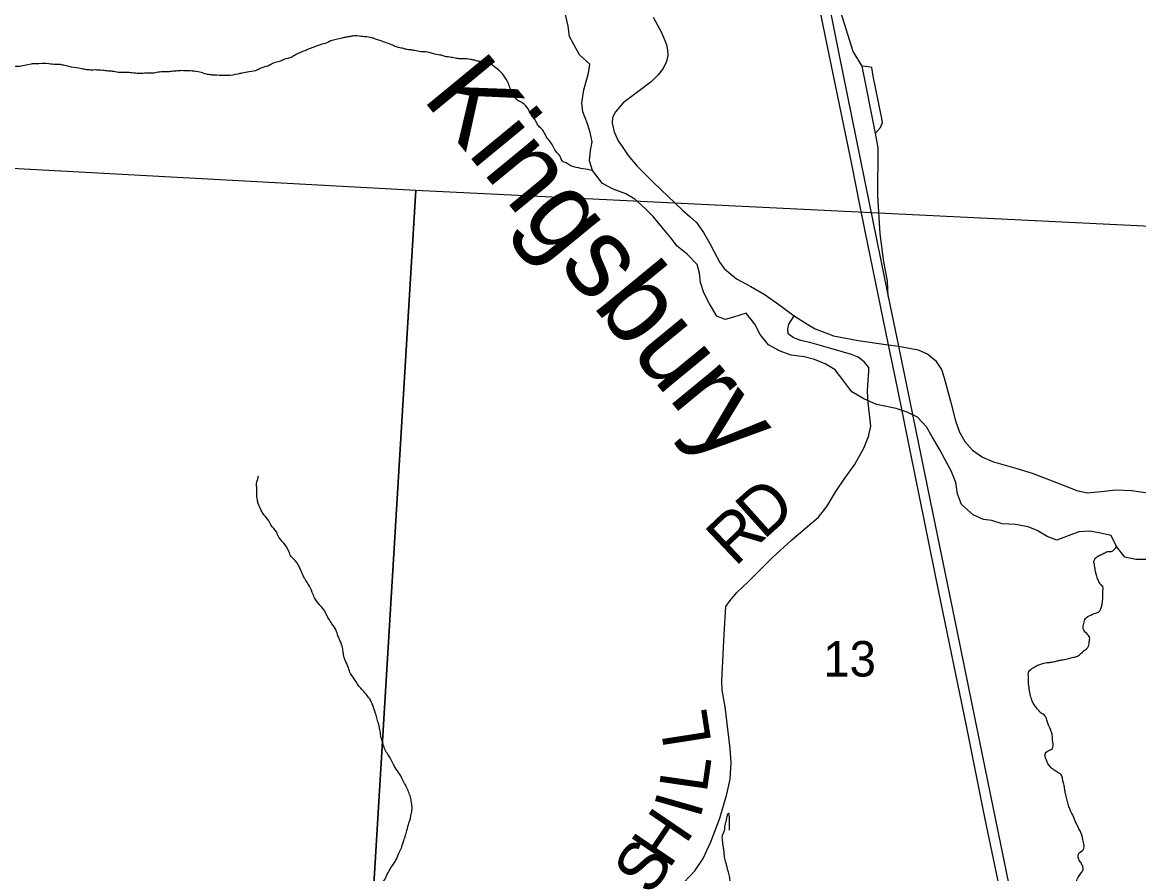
# Model space of a CAD drawing. Extents: x -20.2 to 34, y 0 to 22.
# Drawn here: x 4.435 to 5.753, y 19.304 to 20.309 of the extents above; entities that cross this region are included whole.
import ezdxf

# ---------------------------------------------------------------- set-up
doc = ezdxf.new("R2010")
doc.units = 0
for name, color, linetype in [('GM_X_County_Road', 7, 'Continuous'), ('GM_X_Interchange_Ramps', 7, 'Continuous'), ('GM_X_Minor_River', 7, 'Continuous'), ('GM_X_Minor_River_Text', 7, 'Continuous'), ('GM_X_Section', 7, 'Continuous'), ('GM_X_Section_Text', 7, 'Continuous'), ('GM_X_Township_Road', 7, 'Continuous'), ('GM_X_Township_Road_Text', 7, 'Continuous'), ('GM_X_US_Route', 7, 'Continuous')]:
    doc.layers.add(name, color=color, linetype=linetype)

msp = doc.modelspace()

# ---------------------------------------------------------------- linework, layer by layer
at = {"layer": 'GM_X_County_Road'}
for points in [[(5.1796, 20.3146), (5.1893, 20.2966), (5.1953, 20.2825), (5.1964, 20.2756), (5.1969, 20.2695), (5.1954, 20.2626), (5.1914, 20.2542), (5.1857, 20.2467), (5.1771, 20.2385), (5.1442, 20.2135), (5.135, 20.2031), (5.1315, 20.1964), (5.1313, 20.1896), (5.1338, 20.1793), (5.1383, 20.1688), (5.1429, 20.1623), (5.1502, 20.1516), (5.1607, 20.1388), (5.18, 20.1195), (5.2142, 20.0871), (5.2233, 20.0792), (5.2308, 20.0724), (5.2392, 20.0605), (5.2467, 20.0478), (5.2515, 20.0377), (5.2583, 20.0252), (5.2635, 20.0182), (5.269, 20.0134), (5.2779, 20.0061), (5.2948, 19.9968), (5.3118, 19.987), (5.3215, 19.9803)], [(5.3215, 19.9803), (5.3264, 19.977), (5.346, 19.9624), (5.3624, 19.9521), (5.371, 19.9471), (5.3925, 19.9389), (5.4216, 19.9333), (5.4571, 19.9282), (5.4692, 19.9264), (5.4925, 19.9223), (5.5038, 19.9171), (5.5131, 19.9096), (5.52, 19.8992), (5.5232, 19.889), (5.5307, 19.8616), (5.5365, 19.8384), (5.5411, 19.8249), (5.5475, 19.8142), (5.5567, 19.8038), (5.5686, 19.7954), (5.5813, 19.7899), (5.6033, 19.7839)], [(5.6033, 19.7839), (5.609, 19.7824), (5.6272, 19.7766), (5.6579, 19.765), (5.6799, 19.7561), (5.692, 19.7535), (5.7085, 19.7549), (5.7258, 19.7569), (5.7443, 19.7561), (5.7692, 19.7529), (5.8276, 19.7468), (5.8444, 19.7422), (5.8961, 19.7358), (5.9368, 19.7289), (5.9539, 19.7269), (5.9724, 19.7277), (6.0057, 19.7309)]]:
    msp.add_lwpolyline(points, dxfattribs=at)
at = {"layer": 'GM_X_Interchange_Ramps'}
for points in [[(5.4572, 19.9851), (5.4563, 20.0035), (5.4519, 20.0259), (5.4477, 20.0591), (5.4449, 20.1039), (5.4452, 20.1606), (5.4421, 20.1778), (5.4262, 20.2571), (5.4159, 20.2744), (5.4034, 20.3131), (5.3917, 20.3488), (5.3772, 20.3971), (5.3736, 20.413), (5.3672, 20.4403), (5.3555, 20.4861)], [(5.4421, 20.1778), (5.448, 20.1847), (5.4505, 20.1903), (5.4493, 20.1973), (5.4393, 20.2452), (5.4379, 20.2552), (5.4335, 20.2563), (5.4262, 20.2571)]]:
    msp.add_lwpolyline(points, dxfattribs=at)
at = {"layer": 'GM_X_Minor_River'}
for points in [[(5.7204, 19.703), (5.7079, 19.706), (5.6951, 19.7082), (5.6823, 19.7073), (5.6694, 19.7027), (5.6563, 19.6977), (5.6449, 19.7018), (5.6328, 19.7089), (5.6222, 19.7134), (5.6074, 19.7163), (5.5916, 19.7169), (5.5795, 19.721), (5.5696, 19.7221), (5.5575, 19.7277), (5.5438, 19.7397), (5.5389, 19.7522), (5.5369, 19.7658), (5.5315, 19.7794), (5.5243, 19.7923), (5.5178, 19.8051), (5.509, 19.8194), (5.5025, 19.8315), (5.4915, 19.8428), (5.4794, 19.8488), (5.4665, 19.8529), (5.4533, 19.8558), (5.4434, 19.8577), (5.4283, 19.8644), (5.4143, 19.8726), (5.4048, 19.8851), (5.3945, 19.8986), (5.3827, 19.9058), (5.3702, 19.911), (5.3578, 19.9139), (5.3426, 19.9161), (5.3294, 19.9206), (5.3157, 19.928), (5.3059, 19.9405), (5.2997, 19.9526), (5.2895, 19.9654), (5.2744, 19.9607), (5.2646, 19.958), (5.2547, 19.9621), (5.2463, 19.9765), (5.2395, 19.9893), (5.2356, 20.0018), (5.2344, 20.0127), (5.2317, 20.023), (5.2196, 20.035), (5.2078, 20.0444), (5.2006, 20.0542), (5.1907, 20.0663), (5.1796, 20.0794), (5.1701, 20.0889), (5.158, 20.1001), (5.1474, 20.1061), (5.1326, 20.1117), (5.1197, 20.1184), (5.1079, 20.1339), (5.1045, 20.1452), (5.1055, 20.1574), (5.1077, 20.1676), (5.1054, 20.1786), (5.102, 20.1888), (5.0966, 20.2032), (5.0954, 20.2138), (5.0979, 20.2289), (5.1005, 20.2388), (5.1035, 20.2487), (5.1049, 20.2593), (5.0928, 20.2702), (5.0859, 20.2823), (5.0809, 20.2921), (5.0794, 20.3042), (5.0763, 20.3178)], [(5.7629, 19.6749), (5.7493, 19.6748), (5.7364, 19.6777), (5.7265, 19.6902), (5.7204, 19.703)]]:
    msp.add_lwpolyline(points, dxfattribs=at)
for points in [[(5.1079, 20.1339), (5.0861, 20.1382), (5.0816, 20.1398), (5.077, 20.1428), (5.0725, 20.1448), (5.0703, 20.1497), (5.0658, 20.1551), (5.062, 20.1612), (5.0586, 20.1673), (5.0534, 20.1738), (5.0493, 20.1814), (5.044, 20.1868), (5.0417, 20.1913), (5.0357, 20.1994), (5.032, 20.2066), (5.0252, 20.2135), (5.021, 20.2158), (5.0162, 20.2208), (5.0135, 20.2257), (5.0113, 20.2303), (5.0087, 20.2364), (5.0031, 20.2463), (4.997, 20.2524), (4.9906, 20.2574), (4.9857, 20.2609), (4.9766, 20.2621), (4.9721, 20.2629), (4.9679, 20.2641), (4.9637, 20.2649), (4.9558, 20.2657), (4.9516, 20.2657), (4.9474, 20.2661), (4.9414, 20.2673), (4.9338, 20.2685), (4.9296, 20.2697), (4.922, 20.2709), (4.9164, 20.2728), (4.9054, 20.274), (4.8982, 20.2752), (4.894, 20.276), (4.8879, 20.2768), (4.8838, 20.278), (4.8777, 20.2792), (4.8724, 20.2815), (4.8656, 20.2842), (4.8584, 20.2866), (4.8531, 20.2885), (4.8486, 20.2901), (4.8387, 20.2916), (4.8304, 20.2925), (4.8258, 20.2925), (4.8216, 20.2918), (4.8171, 20.2911), (4.8125, 20.29), (4.8053, 20.2885), (4.7992, 20.2866), (4.7943, 20.2844), (4.7867, 20.2822), (4.7768, 20.2785), (4.7726, 20.277), (4.7684, 20.2751), (4.7581, 20.2706), (4.7532, 20.2676), (4.7436, 20.2647), (4.7387, 20.2624), (4.7315, 20.2606), (4.7269, 20.258), (4.7178, 20.255), (4.7124, 20.2524), (4.7029, 20.2502), (4.6942, 20.2487), (4.6893, 20.2476), (4.6775, 20.2458), (4.6725, 20.2459), (4.6619, 20.2463), (4.6574, 20.2467), (4.6524, 20.2475), (4.6445, 20.2499), (4.6354, 20.2511), (4.6274, 20.2515), (4.6233, 20.2516), (4.6164, 20.2512), (4.6096, 20.2505), (4.605, 20.2502), (4.5971, 20.2499), (4.5906, 20.2488), (4.5792, 20.2485), (4.5728, 20.2482), (4.5644, 20.249), (4.558, 20.2494), (4.5481, 20.2495), (4.5413, 20.2507), (4.5364, 20.2511), (4.5299, 20.2519), (4.52, 20.2524)], [(4.52, 20.2524), (4.5136, 20.2524), (4.5079, 20.2532), (4.5015, 20.2544), (4.4901, 20.2564), (4.4837, 20.258), (4.4787, 20.2588), (4.4742, 20.2588), (4.4662, 20.2596), (4.4503, 20.2597), (4.4453, 20.2594), (4.4374, 20.2576), (4.4301, 20.2565), (4.4237, 20.2562), (4.4184, 20.2558), (4.4142, 20.2558), (4.4051, 20.2552), (4.3956, 20.2545), (4.3823, 20.2534), (4.3778, 20.2531), (4.3721, 20.252), (4.366, 20.2517), (4.3531, 20.2521), (4.3489, 20.2526), (4.344, 20.2526), (4.3383, 20.2538), (4.3288, 20.2554), (4.3231, 20.2562), (4.3155, 20.2566), (4.3091, 20.2574), (4.3049, 20.2578), (4.2977, 20.2587), (4.2924, 20.2591), (4.2879, 20.2591), (4.2822, 20.2595), (4.2753, 20.26), (4.2708, 20.2589), (4.2666, 20.2585), (4.2556, 20.2571), (4.2491, 20.2556), (4.2446, 20.2541), (4.2404, 20.253), (4.2358, 20.2504), (4.227, 20.2452), (4.216, 20.2392), (4.2103, 20.235), (4.2046, 20.2336), (4.2, 20.2298), (4.1954, 20.2279), (4.1905, 20.2265), (4.1859, 20.2238), (4.1798, 20.2216), (4.1756, 20.2197), (4.1688, 20.2156), (4.1615, 20.2119), (4.1509, 20.2074), (4.144, 20.204), (4.1364, 20.2022), (4.1318, 20.1988), (4.1265, 20.1966), (4.1189, 20.1917), (4.1147, 20.1883), (4.1078, 20.1827), (4.1036, 20.1793), (4.099, 20.1751), (4.0929, 20.1733)], [(4.7964, 19.6051), (4.7938, 19.6104), (4.7897, 19.6169), (4.7829, 19.6249), (4.7799, 19.6295), (4.7773, 19.636), (4.7724, 19.6459), (4.7687, 19.6516), (4.7664, 19.6558), (4.7634, 19.663), (4.7571, 19.6737), (4.7525, 19.6783), (4.7496, 19.6844), (4.7432, 19.6947), (4.7379, 19.7012), (4.7349, 19.7073), (4.7285, 19.7157), (4.7248, 19.7222), (4.7188, 19.7295), (4.7165, 19.7337), (4.7135, 19.7409), (4.7124, 19.7451), (4.7117, 19.7523), (4.7118, 19.7591), (4.7114, 19.7637), (4.7126, 19.769), (4.7138, 19.7736)], [(5.6687, 19.3894), (5.6672, 19.3955), (5.6661, 19.3997), (5.6654, 19.405), (5.6643, 19.41), (5.6632, 19.4145), (5.6621, 19.4195), (5.6572, 19.4237), (5.653, 19.4264), (5.6481, 19.4306), (5.6448, 19.4356), (5.6429, 19.4409), (5.6422, 19.4451), (5.646, 19.4492), (5.6509, 19.4518), (5.6514, 19.4594), (5.6507, 19.4678), (5.6496, 19.472), (5.6459, 19.4807), (5.6444, 19.4853), (5.6421, 19.4906), (5.6376, 19.4937), (5.6323, 19.4998), (5.629, 19.504), (5.6267, 19.509), (5.6245, 19.5158), (5.6234, 19.5238), (5.6227, 19.5284), (5.6227, 19.5352), (5.6232, 19.5428), (5.6281, 19.547), (5.6327, 19.5496), (5.6373, 19.5514), (5.6445, 19.5533), (5.6487, 19.5536), (5.6544, 19.5547), (5.6589, 19.5558), (5.6631, 19.5566), (5.6703, 19.558), (5.6757, 19.5595), (5.6806, 19.561), (5.6886, 19.5674), (5.6928, 19.5711), (5.6944, 19.5776), (5.6948, 19.5829), (5.6914, 19.5875), (5.6873, 19.5932), (5.6881, 19.5993), (5.69, 19.6053), (5.6961, 19.6091), (5.7007, 19.6113), (5.7053, 19.6128), (5.7091, 19.62), (5.7099, 19.6242), (5.7104, 19.6325), (5.7104, 19.6374), (5.7108, 19.6416), (5.7074, 19.6462), (5.7048, 19.6508), (5.7029, 19.6565), (5.7018, 19.6607), (5.7008, 19.6679), (5.7, 19.6725), (5.7027, 19.6774), (5.7069, 19.68), (5.7115, 19.6822), (5.7164, 19.6841), (5.7206, 19.6844), (5.7265, 19.6902)], [(4.821, 19.0111), (4.8212, 19.014), (4.8205, 19.0197), (4.8201, 19.0239), (4.819, 19.0285), (4.818, 19.0361), (4.8165, 19.0418), (4.815, 19.0494), (4.8132, 19.0578), (4.8125, 19.0631), (4.811, 19.0688), (4.8091, 19.0764), (4.8073, 19.0821), (4.8058, 19.0871), (4.8043, 19.0916), (4.8028, 19.0958), (4.8017, 19.1008), (4.8003, 19.1053), (4.7988, 19.1103), (4.7973, 19.1194), (4.7974, 19.1247), (4.797, 19.1297), (4.7974, 19.1342), (4.7979, 19.1407), (4.7987, 19.1464), (4.7995, 19.1528), (4.8014, 19.1585), (4.8026, 19.1653), (4.8042, 19.1702), (4.8053, 19.1744), (4.8073, 19.1793), (4.8084, 19.1854), (4.8119, 19.1937), (4.8139, 19.199), (4.8154, 19.2039), (4.8173, 19.2093), (4.8208, 19.2157), (4.8247, 19.2225), (4.8277, 19.2297), (4.8316, 19.2384), (4.8339, 19.2425), (4.8362, 19.2478), (4.8397, 19.2554), (4.8416, 19.2603), (4.8436, 19.2649), (4.8459, 19.2709), (4.849, 19.2758), (4.8528, 19.283), (4.8578, 19.291), (4.8628, 19.2974), (4.8662, 19.3042), (4.8701, 19.311), (4.8735, 19.3163), (4.8766, 19.3212), (4.8797, 19.3291), (4.8828, 19.3356), (4.884, 19.3397), (4.8859, 19.3447), (4.8871, 19.3488), (4.889, 19.3553), (4.8914, 19.364), (4.8929, 19.3681), (4.8937, 19.3727), (4.8949, 19.3788), (4.8946, 19.3864), (4.8935, 19.3928), (4.8916, 19.3993), (4.889, 19.4054), (4.8853, 19.4122), (4.8804, 19.4218), (4.8752, 19.4294), (4.8725, 19.4344), (4.8669, 19.4443), (4.8632, 19.4504), (4.8609, 19.4569), (4.8587, 19.4645), (4.8573, 19.4728), (4.8562, 19.4782), (4.8543, 19.485), (4.8506, 19.4972), (4.848, 19.5044), (4.8454, 19.5098), (4.842, 19.5143), (4.8367, 19.5205), (4.8322, 19.5254), (4.8259, 19.5354), (4.8225, 19.5403), (4.8199, 19.5472), (4.8158, 19.5567), (4.8143, 19.562), (4.8136, 19.5662), (4.8125, 19.5727), (4.8095, 19.5803), (4.8076, 19.5849), (4.8054, 19.5913), (4.8005, 19.599), (4.7964, 19.6051)], [(5.7314, 18.8418), (5.7318, 18.8463), (5.7319, 18.8528), (5.7292, 18.857), (5.7225, 18.8646), (5.7157, 18.8685), (5.707, 18.8731), (5.6998, 18.8792), (5.6949, 18.885), (5.6915, 18.8892), (5.687, 18.8945), (5.6825, 18.898), (5.678, 18.9029), (5.6738, 18.9075), (5.6712, 18.9121), (5.6682, 18.9182), (5.6649, 18.9262), (5.6638, 18.9304), (5.6634, 18.935), (5.6616, 18.941), (5.662, 18.9486), (5.6624, 18.9539), (5.6625, 18.9638), (5.6629, 18.9699), (5.6626, 18.9767), (5.6653, 18.987), (5.6661, 18.9915), (5.6688, 18.996), (5.6735, 19.0097), (5.6746, 19.0146), (5.675, 19.0203), (5.6758, 19.0249), (5.6782, 19.0305), (5.679, 19.0355), (5.679, 19.0423), (5.6783, 19.0469), (5.6757, 19.0533), (5.6727, 19.0617), (5.6686, 19.0655), (5.6648, 19.0705), (5.6626, 19.0777), (5.6611, 19.0831), (5.6608, 19.0888), (5.6593, 19.1002), (5.6594, 19.1043), (5.659, 19.11), (5.6583, 19.1165), (5.6565, 19.1214), (5.6569, 19.1275), (5.6565, 19.1328), (5.6562, 19.1393), (5.6574, 19.1465), (5.6593, 19.1507), (5.6609, 19.156), (5.6606, 19.1624), (5.658, 19.1704), (5.6565, 19.1754), (5.6558, 19.1799), (5.6539, 19.1875), (5.654, 19.1944), (5.6574, 19.2016), (5.6601, 19.2084), (5.6625, 19.2133), (5.667, 19.2159), (5.6712, 19.2182), (5.6758, 19.2212), (5.68, 19.2264), (5.6823, 19.2317), (5.6839, 19.2378), (5.6851, 19.2431), (5.6859, 19.2473), (5.6863, 19.2522), (5.6856, 19.2583), (5.6852, 19.2629), (5.6841, 19.2686), (5.6823, 19.2731), (5.6793, 19.2792), (5.6785, 19.2846), (5.6786, 19.2891), (5.6794, 19.2948), (5.6817, 19.3005), (5.6848, 19.305), (5.6871, 19.3092), (5.6863, 19.3137), (5.6841, 19.3179), (5.6815, 19.3229), (5.6827, 19.3286), (5.6876, 19.3327), (5.6881, 19.3392), (5.6866, 19.3464), (5.6836, 19.3548), (5.681, 19.3597), (5.6788, 19.3643), (5.6754, 19.3723), (5.6724, 19.3784), (5.6705, 19.383), (5.6687, 19.3894)], [(5.4619, 18.7934), (5.4594, 18.7983), (5.459, 18.8033), (5.4583, 18.8116), (5.4585, 18.8363), (5.4589, 18.8428), (5.4594, 18.8485), (5.4598, 18.853), (5.4591, 18.8629), (5.4588, 18.8686), (5.4577, 18.875), (5.4566, 18.88), (5.4551, 18.8891), (5.454, 18.8944), (5.4526, 18.902), (5.4511, 18.9078), (5.4496, 18.9142), (5.4474, 18.9226), (5.4448, 18.9283), (5.4426, 18.9367), (5.4407, 18.942), (5.4392, 18.9473), (5.4378, 18.9542), (5.4363, 18.9588), (5.4356, 18.9641), (5.433, 18.9705), (5.4311, 18.9766), (5.4296, 18.9816), (5.4289, 18.988), (5.4256, 18.9968), (5.4245, 19.0014), (5.4241, 19.0063), (5.4226, 19.0128), (5.4212, 19.0177), (5.4189, 19.0227), (5.4167, 19.028), (5.4137, 19.0364), (5.4107, 19.0436), (5.4089, 19.049), (5.4055, 19.0554), (5.401, 19.0608), (5.3957, 19.0654), (5.3908, 19.0692), (5.3867, 19.0727), (5.3818, 19.0773), (5.3731, 19.0842), (5.3678, 19.0876), (5.3603, 19.0953), (5.352, 19.1014), (5.3471, 19.1068), (5.3433, 19.1114), (5.3399, 19.1159), (5.3313, 19.1232), (5.326, 19.1271), (5.3226, 19.1313), (5.3188, 19.1362), (5.3162, 19.1404), (5.3121, 19.1435), (5.3091, 19.1481), (5.3045, 19.1531), (5.3023, 19.1584), (5.2986, 19.1675), (5.2956, 19.1736), (5.2945, 19.1782), (5.2938, 19.1854), (5.2908, 19.1968), (5.2901, 19.2014), (5.2894, 19.2067), (5.2876, 19.2162), (5.2868, 19.2215), (5.2857, 19.2272), (5.2854, 19.2337), (5.284, 19.2413), (5.2821, 19.2489), (5.2803, 19.2569), (5.2777, 19.2672), (5.2758, 19.2717), (5.2747, 19.2767), (5.2729, 19.2862), (5.2711, 19.2923), (5.2703, 19.298), (5.2689, 19.3045), (5.2674, 19.3098), (5.2663, 19.3143), (5.2652, 19.3185), (5.2637, 19.3261), (5.2634, 19.3303), (5.2626, 19.3353), (5.2616, 19.3432), (5.2616, 19.3497), (5.2639, 19.355), (5.2643, 19.3596), (5.2659, 19.366), (5.2667, 19.3702), (5.2679, 19.3747), (5.2692, 19.3557)]]:
    msp.add_spline(points, degree=3, dxfattribs=at)
at = {"layer": 'GM_X_Section'}
for points in [[(3.8229, 20.1691), (4.8996, 20.1107), (4.8379, 19.0901), (3.7661, 19.1519)], [(4.8996, 20.1107), (5.9839, 20.0577), (5.9253, 19.026), (5.9021, 19.0275), (4.8379, 19.0901)]]:
    msp.add_lwpolyline(points, close=True, dxfattribs=at)
at = {"layer": 'GM_X_Township_Road'}
for points in [[(5.4326, 19.8729), (5.4325, 19.8738), (5.4334, 19.8859), (5.4343, 19.8965), (5.4341, 19.9014), (5.4288, 19.908), (5.4218, 19.9134), (5.4136, 19.9169), (5.3865, 19.9246), (5.3646, 19.9307), (5.3537, 19.9331), (5.3451, 19.9367), (5.3391, 19.9412), (5.3387, 19.9471), (5.3398, 19.9526), (5.346, 19.9624)], [(5.2094, 19.287), (5.229, 19.3074), (5.2385, 19.322), (5.2476, 19.3416), (5.2583, 19.3698), (5.2668, 19.398), (5.2706, 19.4156), (5.2718, 19.4351), (5.2706, 19.452), (5.2647, 19.5012), (5.261, 19.5208), (5.2606, 19.5317), (5.2636, 19.5865), (5.2656, 19.6193), (5.2706, 19.6266), (5.2786, 19.6359), (5.2916, 19.6487), (5.3203, 19.6767), (5.3432, 19.6981), (5.3749, 19.7249), (5.3845, 19.7375), (5.3954, 19.755), (5.4059, 19.7707), (5.4172, 19.7864), (5.4282, 19.8064), (5.4339, 19.8199), (5.4366, 19.8322), (5.435, 19.8463), (5.4336, 19.8595), (5.4326, 19.8729)]]:
    msp.add_lwpolyline(points, dxfattribs=at)
at = {"layer": 'GM_X_US_Route'}
for points in [[(5.2581, 20.9), (5.2602, 20.8883), (5.2797, 20.7952), (5.3056, 20.6696), (5.3123, 20.6365), (5.3246, 20.5769), (5.3452, 20.4766), (5.3466, 20.4693), (5.3496, 20.4532), (5.3627, 20.39), (5.3822, 20.2933), (5.414, 20.1393), (5.4234, 20.0934), (5.4296, 20.0622), (5.4571, 19.9282), (5.4677, 19.8772), (5.4744, 19.8444), (5.4831, 19.8015), (5.5165, 19.6366), (5.5491, 19.4787), (5.5708, 19.3706), (5.5897, 19.2804)], [(5.2703, 20.9), (5.2928, 20.7901), (5.3304, 20.6075), (5.3478, 20.5228), (5.3555, 20.4861), (5.3609, 20.46), (5.3717, 20.405), (5.3904, 20.3127), (5.3983, 20.2736), (5.4347, 20.0951), (5.4572, 19.9851), (5.4692, 19.9264), (5.5062, 19.7462), (5.5384, 19.5891), (5.5681, 19.4445), (5.5994, 19.2912)]]:
    msp.add_lwpolyline(points, dxfattribs=at)

# ---------------------------------------------------------------- texts
at = {"layer": 'GM_X_Minor_River_Text'}
msp.add_text('Kingsbury', height=0.09471, rotation=309.4251, dxfattribs=at).set_placement((4.9059, 20.2191))
at = {"layer": 'GM_X_Section_Text'}
msp.add_text('13', height=0.04186, rotation=0, dxfattribs=at).set_placement((5.3804, 19.5368))
at = {"layer": 'GM_X_Township_Road_Text'}
for s, rotation, p in [('D', 41.8353, (5.3098, 19.6972)), ('R', 43.4985, (5.2763, 19.6654)), ('L', 98.8302, (5.2486, 19.4587)), ('L', 81.7847, (5.2427, 19.3983)), ('I', 73.9972, (5.2345, 19.3676)), ('H', 55.8522, (5.1981, 19.3085)), ('S', 56.2058, (5.1768, 19.2767))]:
    msp.add_text(s, height=0.0568, rotation=rotation, dxfattribs=at).set_placement(p)

doc.saveas('drawing.dxf')
